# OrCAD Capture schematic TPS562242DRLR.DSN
size A
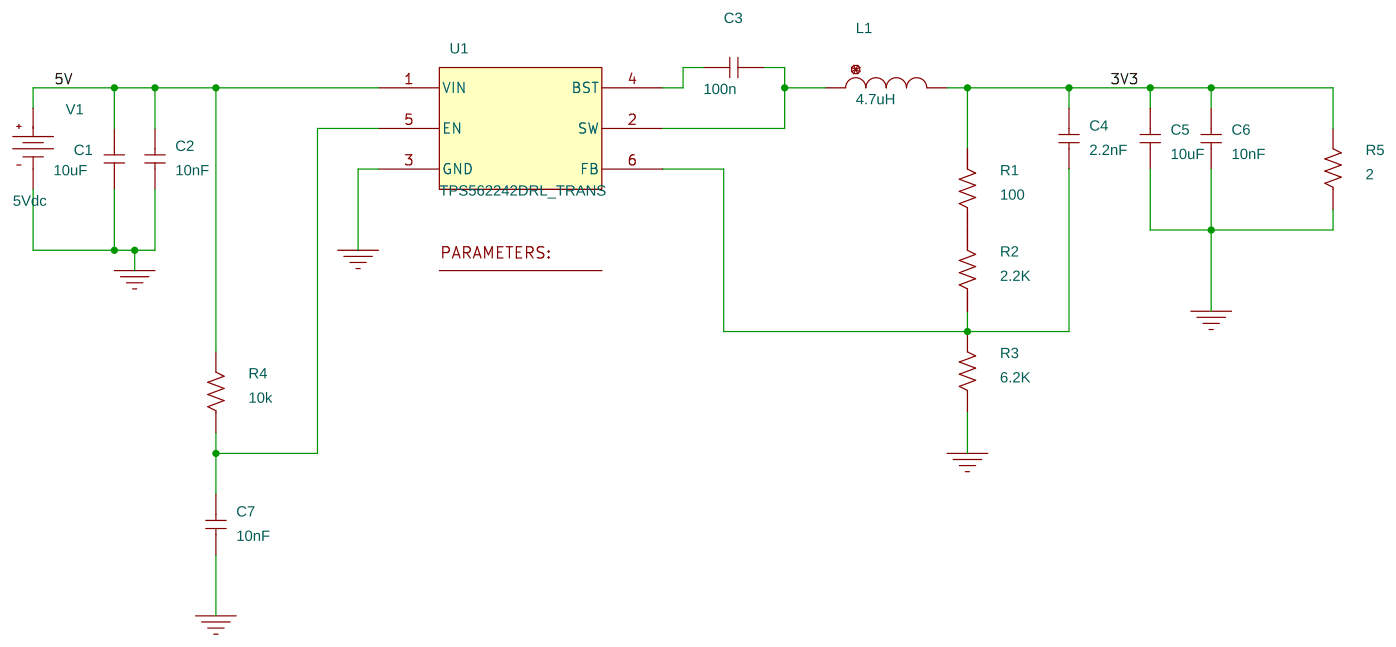
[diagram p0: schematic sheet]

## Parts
1  PARAM
C1  10uF  [cap196]
C2  10nF  [cap196]
C3  100n  [cap196]
C4  2.2nF  [cap196]
C5  10uF  [cap196]
C6  10nF  [cap196]
C7  10nF  [cap196]
L1  4.7uH  [DISC350x175LS200x100034]
R1  100  [AXRC05]
R2  2.2K  [AXRC05]
R3  6.2K  [AXRC05]
R4  10k  [AXRC05]
R5  2  [AXRC05]
U1  TPS562242DRL_TRANS
V1  VDC

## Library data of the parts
1 = PARAM
C1-C7 = C
L1 = L
R1-R5 = R
U1 = TPS562242_TRANS_0
V1 = VDC: DC: 5Vdc

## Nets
3V3: C4.2 C5.2 C6.2 L1.2 R1.2 R5.2
5V: C1.2 C2.2 R4.2 U1.1(VIN) V1.0(+)
0: C1.1 C2.1 C5.1 C6.1 C7.1 R3.1 R5.1 U1.3(GND) V1.1(-)
N00460: C4.1 R2.1 R3.2 U1.6(FB)
N00579: C3.1 U1.4(BST)
N00591: C3.2 L1.1 U1.2(SW)
N00800: R1.1 R2.2
N01127: C7.2 R4.1 U1.5(EN)
